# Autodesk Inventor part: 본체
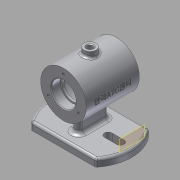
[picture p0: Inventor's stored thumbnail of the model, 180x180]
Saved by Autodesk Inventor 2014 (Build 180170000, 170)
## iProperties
Created: 2017-12
Part Number: 본체
Material: 알루미늄 6061
Document SubType Name: Modeling
Designer: user
Density: 2.71 g/cm^3
Appearance: 알루미늄 - 평지
Mass: 467.692 g
Surface Area: 486.474 cm^2
Volume: 172.58 cm^3
Author: user
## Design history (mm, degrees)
sketch "스케치1"
  geometry: C1 r 30 at (0, 0); 1 further point
  constraints: 1 centre point, 1 coincident
  dimensions: "d0" = 60 diameter of C1
extrude "돌출1" new body sketch "스케치1" stored distance "d1" = 70; taper "d2" = 0 deg
sketch "스케치2"
  geometry: L1 (30, -35)-(-30, -35) reference; L2 (-30, -35)-(-30, 35) reference; L3 (-30, 35)-(30, 35) reference; L4 (30, 35)-(30, -35) reference; L5 (0, 35)-(0, -35); L6 (0, 35)-(16, 35); L7 (16, 35)-(16, 23); L8 (16, 23)-(14, 23); L9 (14, 23)-(14, 20); L10 (14, 20)-(25, 20); L11 (25, 20)-(25, -20); L12 (25, -20)-(14, -20); L13 (14, -20)-(14, -23); L14 (14, -23)-(16, -23); L15 (16, -23)-(16, -35); L16 (0, -35)-(16, -35); 1 further point
  constraints: 24 end point, 5 parallel, 3 perpendicular, 2 collinear, 2 midpoint, 2 point on line
  dimensions: "d3" = 40 distance of L10.end L11.end; "d4" = 12 distance of L14.end L15.end; "d5" = 12 distance of L6.end L7.end; "d6" = 3 distance of L8.end L9.end; "d7" = 32 diameter of L7 L5; "d8" = 50 diameter of L11 L5; "d9" = 32 diameter of L15 L5; "d10" = 28 diameter of L13 L5; "d11" = 28 diameter of L9 L5
revolve "회전1" sketch "스케치2" stored, may be unused: angle "d12" = 90 deg
node "작업 평면1"
sketch "스케치3"
  geometry: C1 r 55 at (0, 0); 1 further point
  constraints: 1 centre point, 1 coincident
  dimensions: "d14" = 110 diameter of C1
extrude "돌출2" join sketch "스케치3" distance "d15" = 10; taper "d16" = 0 deg
sketch "스케치4"
  geometry: L1 (-42.426, 35)-(42.426, 35); A1 r 55 centre (0, 0) between (-42.426, 35) and (42.426, 35) reference; A2 r 55 centre (0, 0) between (42.426, 35) and (-42.426, 35)
  constraints: 4 point on circle, 2 end point, 1 centre point, 1 concentric, 1 horizontal
  dimensions: "d18" = 35 distance from line of A1.centre L1
extrude "돌출3" cut sketch "스케치4" stored distance "d19" = 10; taper "d20" = 0 deg
sketch "스케치5"
  geometry: L1 (42.426, 35)-(-42.426, 35) reference; L2 (0, -15)-(0, 15); L3 (-5, -15)-(-5, 15); L4 (5, 15)-(5, -15); A1 r 55 centre (0, 0) between (-42.426, 35) and (-42.426, -35) reference; A2 r 5 centre (0, -15) between (-5, -15) and (5, -15); A3 r 5 centre (0, 15) between (5, 15) and (-5, 15)
  constraints: 8 end point, 4 point on circle, 4 tangent, 2 centre point, 1 midpoint, 1 parallel, 1 perpendicular
  dimensions: "d21" = 30 distance of L2.start L2.end; "d22" = 5 radius of A2
extrude "돌출4" join sketch "스케치5" stored distance "d23" = 10; taper "d24" = 0 deg
sketch "스케치6"
  geometry: L1 (-42.426, -35)-(42.426, -35) reference; L2 (-40, 0)-(-24, 0); L3 (-40, -5)-(-24, -5); L4 (-24, 5)-(-40, 5); A1 r 55 centre (0, 0) between (42.426, -35) and (42.426, 35) reference; A2 r 5 centre (-40, 0) between (-40, 5) and (-40, -5); A3 r 5 centre (-24, 0) between (-24, -5) and (-24, 5); 1 further point
  constraints: 8 end point, 4 point on circle, 4 tangent, 2 centre point, 2 parallel, 1 horizontal alignment, 1 midpoint
  dimensions: "d25" = 16 distance of L4.start L4.end; "d27" = 5 radius of A2; "d30" = 24 distance of A1.centre L2.end
extrude "돌출5" cut sketch "스케치6" stored distance "d28" = 10; taper "d29" = 0 deg
sketch "스케치7" dims "d31" = 46
  geometry: C1 r 16 at (0, 0) reference; C2 r 30 at (0, 0) reference; 2 further points
  constraints: 2 vertical alignment, 1 coincident, 2 other
hole "구멍1" sketch "스케치7" at (0, 23) diameter "d32" = 3.242; stored, may be unused: countersink angle "d36" = 90 deg, drill point angle "d38" = 118 deg; dims "d33" = 8, "d34" = 4, "d35" = 2, "d37" = 10
fillet "모깎기1" dims "d42" = 3
fillet "모깎기2" dims "d43" = 0.3
node "작업 평면2"
sketch "스케치8"
  geometry: C1 r 8 at (0, 0); 1 further point
  constraints: 1 centre point, 1 coincident
  dimensions: "d45" = 16 diameter of C1
extrude "돌출6" join sketch "스케치8" stored distance "d46" = 10; taper "d47" = 0 deg
sketch "스케치9"
  geometry: C1 r 8 at (0, 0) reference; C2 r 4 at (0, 0)
  constraints: 1 centre point, 1 coincident
  dimensions: "d48" = 8 diameter of C2
extrude "돌출7" cut sketch "스케치9" stored distance "d49" = 10; taper "d50" = 0 deg
chamfer "모따기1" distance "d51" = 1; stored, may be unused: second distance "d52" = 2, angle "d53" = 45 deg
chamfer "모따기2" distance "d54" = 1; stored, may be unused: second distance "d55" = 2, angle "d56" = 45 deg
chamfer "모따기3" distance "d57" = 1; stored, may be unused: second distance "d58" = 2, angle "d59" = 45 deg
fillet "모깎기3" dims "d60" = 5
fillet "모깎기4" dims "d61" = 3
fillet "모깎기5" dims "d62" = 3
node "작업 평면4"
sketch "스케치11"
  geometry: L1 (-50, 77)-(-50, 17) reference; 2 further points
  constraints: 1 other
  dimensions: "d69" = 35 distance from line of L1 point (-15, 47); "d70" = 30 vertical distance of L1.start point (-15, 47)
feature "엠보싱2" sketch "스케치11" dims "d2" = 0, "d13" = -62, "d71" = 0.5, "d72" = 0
node "솔리드1"
mirror "대칭1"
mirror "대칭2"
pattern_circular "원형 패턴1" dims angle "d40" = 360 deg
mirror "대칭3"
node "절단 모서리 투영1"
other parameters: "d44" = -99
